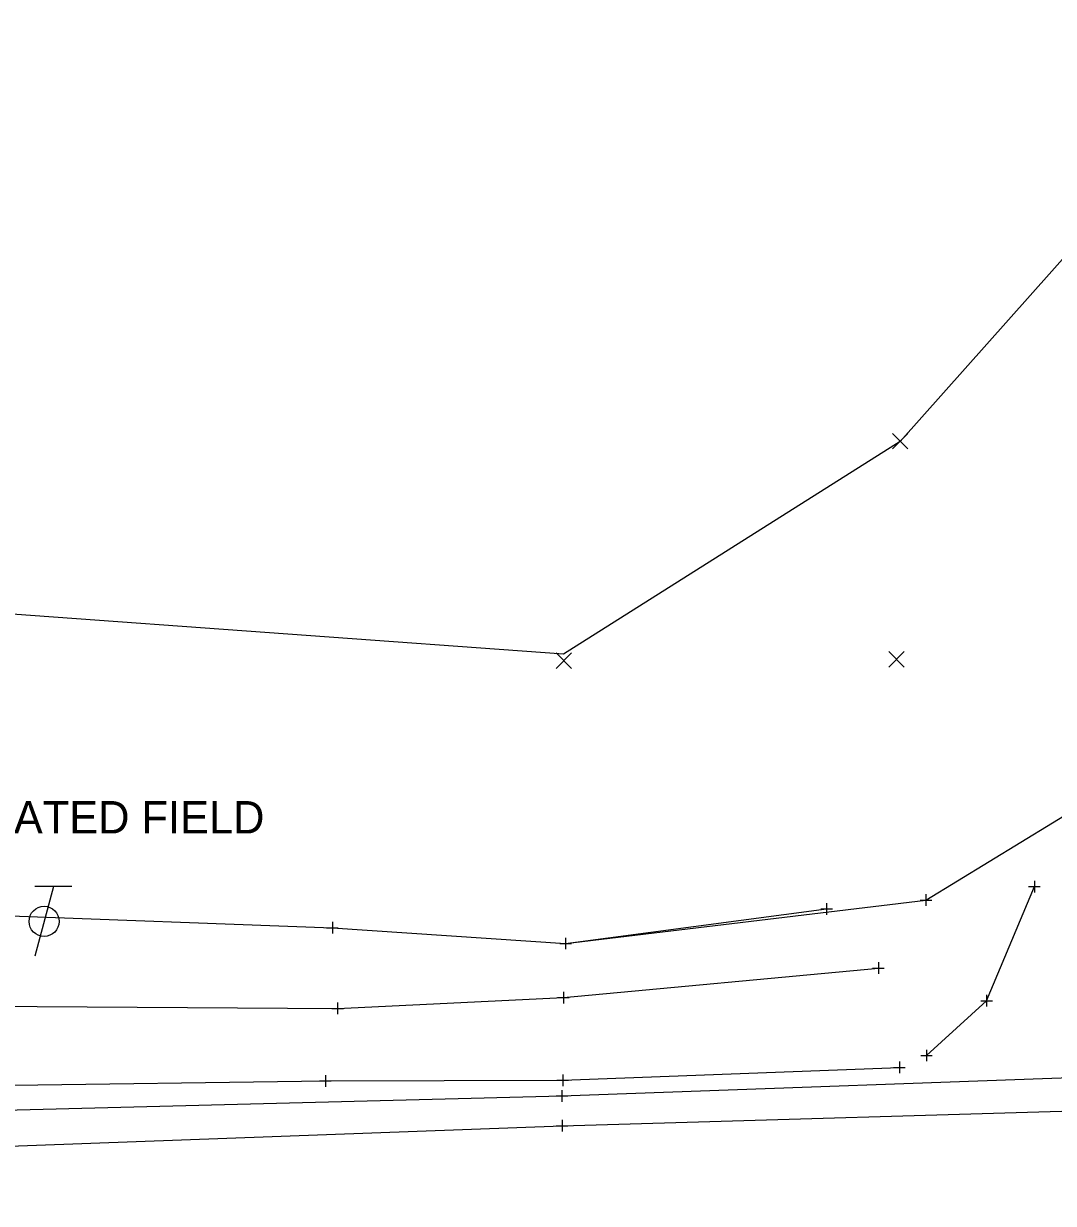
# Model space of a CAD drawing. Extents: x 211013 to 211654, y 505587 to 505872.
# Drawn here: x 211162.3 to 211251.2, y 505723.9 to 505825.7 of the extents above; entities that cross this region are included whole.
import ezdxf

# ---------------------------------------------------------------- set-up
doc = ezdxf.new("R2010")
doc.units = 0
for name, color, linetype in [('CL_X_RW', 7, 'Continuous'), ('DV_X_Section_VMS_Line', 7, 'Continuous'), ('GE_X_Alignment', 7, 'Continuous'), ('GE_X_Alignment_100_Curve_Data', 7, 'Continuous'), ('GE_X_Alignment_100_Stations', 7, 'Continuous'), ('GE_X_Alignment_500_Curve_Data', 7, 'Continuous'), ('GE_X_Alignment_500_Stations', 7, 'Continuous'), ('MT_X_Drums', 7, 'Continuous'), ('PM_X_Edge_Line', 7, 'Continuous'), ('RW_X_Esmt_SH', 7, 'Continuous'), ('SV_X_Terrain_Boundary', 7, 'Continuous'), ('SV_X_Text', 7, 'Continuous')]:
    doc.layers.add(name, color=color, linetype=linetype)

msp = doc.modelspace()

# ---------------------------------------------------------------- linework, layer by layer
at = {"layer": 'CL_X_RW'}
for p, q in [((211166.5, 505751.22), (211163.3, 505751.22)), ((211164.9, 505751.22), (211163.3, 505745.22))]:
    msp.add_line(p, q, dxfattribs=at)
msp.add_circle((211164.1, 505748.22), 1.3, dxfattribs=at)
at = {"layer": 'DV_X_Section_VMS_Line'}
for p, q in [((211249.59, 505751.72), (211249.59, 505750.72)), ((211249.09, 505751.22), (211250.09, 505751.22)), ((211249.59, 505751.22), (211249.59, 505751.22)), ((211231.65, 505749.79), (211231.65, 505748.79)), ((211239.73, 505750.06), (211240.73, 505750.06)), ((211240.23, 505750.56), (211240.23, 505749.56)), ((211240.23, 505750.06), (211240.23, 505750.06)), ((211231.15, 505749.29), (211232.15, 505749.29)), ((211231.65, 505749.29), (211231.65, 505749.29)), ((211188.49, 505747.67), (211189.49, 505747.67)), ((211188.49, 505747.67), (211189.49, 505747.67)), ((211188.99, 505748.17), (211188.99, 505747.17)), ((211188.99, 505748.17), (211188.99, 505747.17)), ((211188.99, 505747.67), (211188.99, 505747.67)), ((211188.99, 505747.67), (211188.99, 505747.67)), ((211209.12, 505746.81), (211209.12, 505745.81)), ((211209.12, 505746.81), (211209.12, 505745.81)), ((211208.62, 505746.31), (211209.62, 505746.31)), ((211208.62, 505746.31), (211209.62, 505746.31)), ((211209.12, 505746.31), (211209.12, 505746.31)), ((211209.12, 505746.31), (211209.12, 505746.31)), ((211236.13, 505744.69), (211236.13, 505743.69)), ((211235.63, 505744.19), (211236.63, 505744.19)), ((211236.13, 505744.19), (211236.13, 505744.19)), ((211208.43, 505741.64), (211209.43, 505741.64)), ((211208.93, 505742.14), (211208.93, 505741.14)), ((211208.93, 505741.64), (211208.93, 505741.64)), ((211245.47, 505741.87), (211245.47, 505740.87)), ((211188.94, 505740.71), (211189.94, 505740.71)), ((211189.44, 505741.21), (211189.44, 505740.21)), ((211189.44, 505740.71), (211189.44, 505740.71)), ((211244.97, 505741.37), (211245.97, 505741.37)), ((211245.47, 505741.37), (211245.47, 505741.37)), ((211239.78, 505736.64), (211240.78, 505736.64)), ((211240.28, 505737.14), (211240.28, 505736.14)), ((211240.28, 505736.64), (211240.28, 505736.64)), ((211237.44, 505735.61), (211238.44, 505735.61)), ((211237.94, 505736.11), (211237.94, 505735.11)), ((211237.94, 505735.61), (211237.94, 505735.61)), ((211187.88, 505734.44), (211188.88, 505734.44)), ((211188.38, 505734.94), (211188.38, 505733.94)), ((211188.38, 505734.44), (211188.38, 505734.44)), ((211208.37, 505734.5), (211209.37, 505734.5)), ((211208.87, 505735), (211208.87, 505734)), ((211208.87, 505734.5), (211208.87, 505734.5)), ((211208.81, 505733.65), (211208.81, 505732.65)), ((211208.31, 505733.15), (211209.31, 505733.15)), ((211208.81, 505733.15), (211208.81, 505733.15)), ((211208.32, 505730.58), (211209.32, 505730.58)), ((211208.32, 505730.58), (211209.32, 505730.58)), ((211208.82, 505731.08), (211208.82, 505730.08)), ((211208.82, 505731.08), (211208.82, 505730.08)), ((211208.82, 505730.58), (211208.82, 505730.58)), ((211208.82, 505730.58), (211208.82, 505730.58))]:
    msp.add_line(p, q, dxfattribs=at)
at = {"layer": 'GE_X_Alignment'}
msp.add_lwpolyline([(211013.74, 505757.44), (211039.35, 505757.76), (211089.44, 505745.11), (211110.4, 505747.3), (211138.84, 505748.86), (211159.65, 505748.75), (211188.99, 505747.67), (211209.12, 505746.31), (211240.23, 505750.06), (211264.84, 505765.09), (211274.1, 505775.82), (211283.53, 505792.47), (211291.8, 505810.61), (211301.47, 505825.74)], dxfattribs=at)
at = {"layer": 'GE_X_Alignment_100_Curve_Data'}
msp.add_lwpolyline([(211014.9, 505728.85), (211059.58, 505729.76), (211084.8, 505731.17), (211109.64, 505731.61), (211140.67, 505733.25), (211159.39, 505734.06), (211188.38, 505734.44), (211208.87, 505734.5), (211237.94, 505735.61)], dxfattribs=at)
at = {"layer": 'GE_X_Alignment_100_Stations'}
for points in [[(211056.71, 505751.14), (211057.33, 505745.65), (211063.2, 505739.83), (211071.49, 505738.1), (211085.28, 505737.62), (211109.68, 505739.14), (211139.54, 505738.66), (211159.15, 505740.9), (211189.44, 505740.71), (211208.93, 505741.64), (211236.13, 505744.19)], [(211070.22, 505746.02), (211079.42, 505742.98), (211089.44, 505745.11), (211110.4, 505747.3), (211138.84, 505748.86), (211159.65, 505748.75), (211188.99, 505747.67), (211209.12, 505746.31), (211231.65, 505749.29)]]:
    msp.add_lwpolyline(points, dxfattribs=at)
at = {"layer": 'GE_X_Alignment_500_Curve_Data'}
msp.add_lwpolyline([(211014.94, 505724.38), (211059, 505725.8), (211109.78, 505727.2), (211159.51, 505728.76), (211208.82, 505730.58), (211259.8, 505732.07), (211285.15, 505733.09), (211309.66, 505733.86), (211334.86, 505734.83), (211359.19, 505735.69), (211410.23, 505737.38), (211459.71, 505738.84), (211509.76, 505740.37), (211559.97, 505741.95), (211609.77, 505743.95), (211648.34, 505745.17)], dxfattribs=at)
at = {"layer": 'GE_X_Alignment_500_Stations'}
msp.add_lwpolyline([(211014.96, 505726.7), (211059.16, 505728.21), (211109.79, 505730.12), (211159.49, 505731.89), (211208.81, 505733.15), (211259.88, 505734.99), (211284.98, 505735.99), (211309.59, 505736.29), (211335.02, 505737.47), (211359.19, 505738.25), (211410.26, 505740.04), (211459.78, 505741.71), (211509.56, 505743.25), (211560.07, 505744.76), (211609.93, 505746.61), (211648.16, 505748.08)], dxfattribs=at)
at = {"layer": 'MT_X_Drums'}
msp.add_lwpolyline([(211240.28, 505736.64), (211245.47, 505741.37), (211249.59, 505751.22)], dxfattribs=at)
at = {"layer": 'PM_X_Edge_Line'}
msp.add_lwpolyline([(211014.94, 505724.38), (211059, 505725.8), (211109.78, 505727.2), (211159.51, 505728.76), (211208.82, 505730.58), (211259.8, 505732.07), (211285.15, 505733.09), (211309.66, 505733.86), (211334.86, 505734.83), (211359.19, 505735.69), (211410.23, 505737.38), (211459.71, 505738.84), (211509.76, 505740.37), (211559.97, 505741.95), (211609.77, 505743.95), (211648.34, 505745.17)], dxfattribs=at)
at = {"layer": 'RW_X_Esmt_SH'}
for p, q in [((211237.34, 505789.01), (211238.68, 505790.34)), ((211237.34, 505790.34), (211238.68, 505789.01)), ((211208.3, 505770.07), (211209.63, 505771.4)), ((211208.3, 505771.4), (211209.63, 505770.07)), ((211237.03, 505770.17), (211238.36, 505771.51)), ((211237.03, 505771.51), (211238.36, 505770.17))]:
    msp.add_line(p, q, dxfattribs=at)
at = {"layer": 'SV_X_Terrain_Boundary'}
msp.add_lwpolyline([(211258.57, 505812.76), (211238.01, 505789.67), (211208.95, 505771.3), (211161.33, 505774.75), (211112.02, 505773.7), (211055.47, 505773.4), (211013.95, 505769.7), (211014.38, 505747.97), (211015.17, 505738.62), (211015.65, 505681.68), (211013.46, 505661.46), (211064.36, 505661.96), (211109.35, 505661.26), (211151.86, 505632.96), (211149.18, 505606.08), (211186.51, 505603.87), (211206.35, 505610.45), (211218.51, 505613.39), (211247.2, 505610.15), (211268.66, 505610.6)], dxfattribs=at)

# ---------------------------------------------------------------- texts
at = {"layer": 'SV_X_Text'}
msp.add_text('CULTIVATED FIELD', height=2.8, dxfattribs=at).set_placement((211148.17, 505755.81))

doc.saveas('drawing.dxf')
